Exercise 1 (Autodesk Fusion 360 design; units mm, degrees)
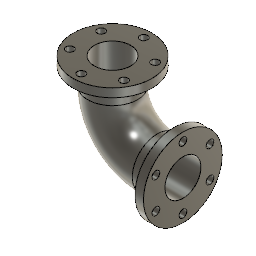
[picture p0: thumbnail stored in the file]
sketch "Sketch1" plane through (0, 0, 0) normal (0, 1, 0) x axis (1, 0, 0)
  line L1 (0, 100) -> (0, 0)
  line L2 (360, 360) -> (260, 360)
  arc A1 centre (260, 100) radius 260 clockwise from (0, 100) to (260, 360)
  point P1 (0, 0)
  point P2 (0, 0)
  point P3 (0, 100)
  point P4 (260, 360)
  point P6 (360, 360)
  coincident P1 P2
  vertical L1
  tangent L1 A1
  perpendicular L1 L2
  tangent A1 L2
  dimension "d1" distance P2 P3 = 100
  dimension "d2" distance P4 P6 = 100
  dimension "d3" radius A1 = 260
sketch "Sketch2" plane through (0, 0, 0) normal (0, 0, 1) x axis (1, 0, 0)
  circle C1 centre (0, 0) radius 145
  circle C2 centre (0, 0) radius 105
  point P1 (0, 0)
  point P2 (0, 0)
  coincident P1 P2
  concentric C1 C2
  dimension "d4" diameter C1 = 290
  dimension "d5" diameter C2 = 210
sweep "Sweep1" sketch "Sketch2" + "Sketch4" TwistAngle 0 TaperAngle 0
sketch "Sketch3" plane through (0, 0, 0) normal (0, 0, 1) x axis (-1, 0, 0)
  circle C1 centre (0, 0) radius 105
  circle C2 centre (0, 0) radius 145
  circle C3 centre (0, 0) radius 230
  point P1 (0, 0)
  point P3 (0, 0)
  coincident P1 P3
  dimension "d12" diameter C3 = 460
extrude "Extrude1" add sketch "Sketch3" along normal blind 50
sketch "Sketch4" plane through (0, 0, 50) normal (0, 0, 1) x axis (-1, 0, 0)
  circle C1 centre (0, 0) radius 105
  circle C2 centre (0, 0) radius 230
  circle C3 centre (0, -182) radius 22.5
  point P1 (0, 0)
  point P3 (0, -182)
  vertical P1 P3
  dimension "d15" diameter C3 = 45
  dimension "d16" distance P1 P3 = 182
extrude "Extrude3" cut sketch "Sketch4" profile of C3 to an object
circular_pattern "C-Pattern1" sketch "Sketch4" TotalAngle 360
sketch "Sketch5" plane through (360, 0, 0) normal (1, 0, 0) x axis (0, 1, 0)
  circle C1 centre (0, -360) radius 105
  circle C2 centre (0, -360) radius 145
  circle C3 centre (0, -360) radius 230
  concentric C1 C3
  dimension "d23" diameter C3 = 460
extrude "Extrude4" add sketch "Sketch5" along normal blind 50
sketch "Sketch6" plane through (410, 0, 0) normal (1, 0, 0) x axis (0, 1, 0)
  circle C1 centre (0, -360) radius 105
  circle C2 centre (0, -360) radius 230
  circle C3 centre (0, -542) radius 22.5
  point P1 (0, 0)
  point P3 (0, -542)
  point P2 (0, -360)
  vertical P1 P3
  dimension "d26" diameter C3 = 45
  dimension "d27" distance P2 P3 = 182
extrude "Extrude5" cut sketch "Sketch6" profile of C3 to an object
circular_pattern "C-Pattern2" sketch "Sketch4" TotalAngle 360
